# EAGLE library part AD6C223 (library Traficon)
1 Form C Solid state relay (SPDT)
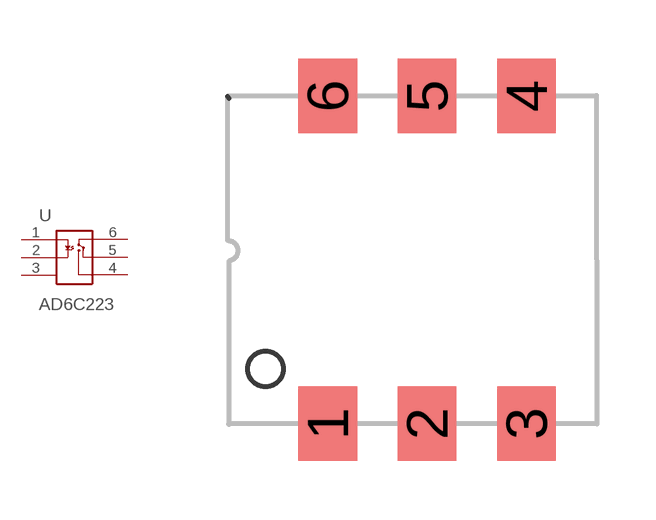
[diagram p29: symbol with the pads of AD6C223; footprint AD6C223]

Designator prefix -

## AD6C223  [AD6C223]
1  1  in
2  2  in
3  3  nc
4  4  pas
5  5  pas
6  6  pas

## Footprint AD6C223 (pad centres in mm)
smd 1.499 x 1.905: 1 2.54,-8.382; 2 5.08,-8.382; 3 7.62,-8.382; 4 7.62,0; 5 5.08,0; 6 2.54,0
